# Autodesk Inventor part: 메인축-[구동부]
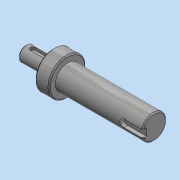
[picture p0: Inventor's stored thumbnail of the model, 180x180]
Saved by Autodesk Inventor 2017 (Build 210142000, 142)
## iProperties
Created: 2018-09
Part Number: 메인축-[구동부]
Document SubType Name: Modeling
Density: 7.86 g/cm^3
Material: 강철, 연강
Appearance: 강철
Mass: 251.954 g
Surface Area: 77.4403 cm^2
Volume: 32.0552 cm^3
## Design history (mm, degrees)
sketch "스케치1"
  geometry: L1 (34.997, -37.5)-(34.997, -77.5) reference; L2 (46.5, -38.401)-(46.5, -76.599) reference; L3 (12.497, -57.5)-(116.5, -57.5); L4 (12.497, -63.5)-(34.997, -63.5); L5 (34.997, -72.5)-(46.5, -72.5); L6 (46.5, -67.5)-(116.5, -67.5); L7 (116.5, -67.5)-(116.5, -57.5); L8 (12.497, -63.5)-(12.497, -57.5); 2 further points
  constraints: 12 end point, 5 point on line, 4 perpendicular, 1 midpoint, 1 parallel
  dimensions: "d0" = 20 diameter of L6 L3; "d1" = 30 diameter of L5 L3; "d2" = 22.5 distance of L4.start L4.end; "d3" = 70 distance of L6.start L6.end; "d5" = 12 diameter of L4 L3
revolve "회전1" sketch "스케치1" stored, may be unused: angle "d4" = 90 deg
chamfer "모따기1" distance "d6" = 1; stored, may be unused: second distance "d7" = 2, angle "d8" = 45 deg
node "작업 평면1"
sketch "스케치2"
  geometry: L1 (-11.25, -5)-(-11.25, 5) reference; L2 (-5.25, 2)-(4.75, 2); L3 (4.75, -2)-(-5.25, -2); A1 r 2 centre (4.75, 0) between (4.75, -2) and (4.75, 2); A2 r 2 centre (-5.25, 0) between (-5.25, 2) and (-5.25, -2); 2 further points
  constraints: 4 end point, 4 point on circle, 4 tangent, 2 centre point, 1 horizontal alignment, 1 midpoint, 1 parallel, 1 perpendicular
  dimensions: "d9" = 4 distance between parallel lines of L3 L2; "d10" = 14 dimension on A1 A2; "d11" = 4 distance edge to line of A2 L1
extrude "돌출1" cut sketch "스케치2" distance "d12" = 2.5; taper "d13" = 0 deg
node "작업 평면2"
sketch "스케치3"
  geometry: L1 (35, 9)-(35, -9) reference; L2 (35, 3)-(20, 3); L3 (20, -3)-(35, -3); A1 r 3 centre (20, 0) between (20, 3) and (20, -3); 2 further points
  constraints: 4 end point, 2 perpendicular, 2 point on circle, 2 point on line, 2 tangent, 1 centre point, 1 horizontal alignment, 1 midpoint
  dimensions: "d14" = 6 distance between parallel lines of L3 L2; "d15" = 18 dimension on A1 L1
extrude "돌출2" cut sketch "스케치3" distance "d16" = 3.5; taper "d17" = 0 deg
node "솔리드1"
node "참조1"
node "참조2"
